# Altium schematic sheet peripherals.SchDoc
size A3
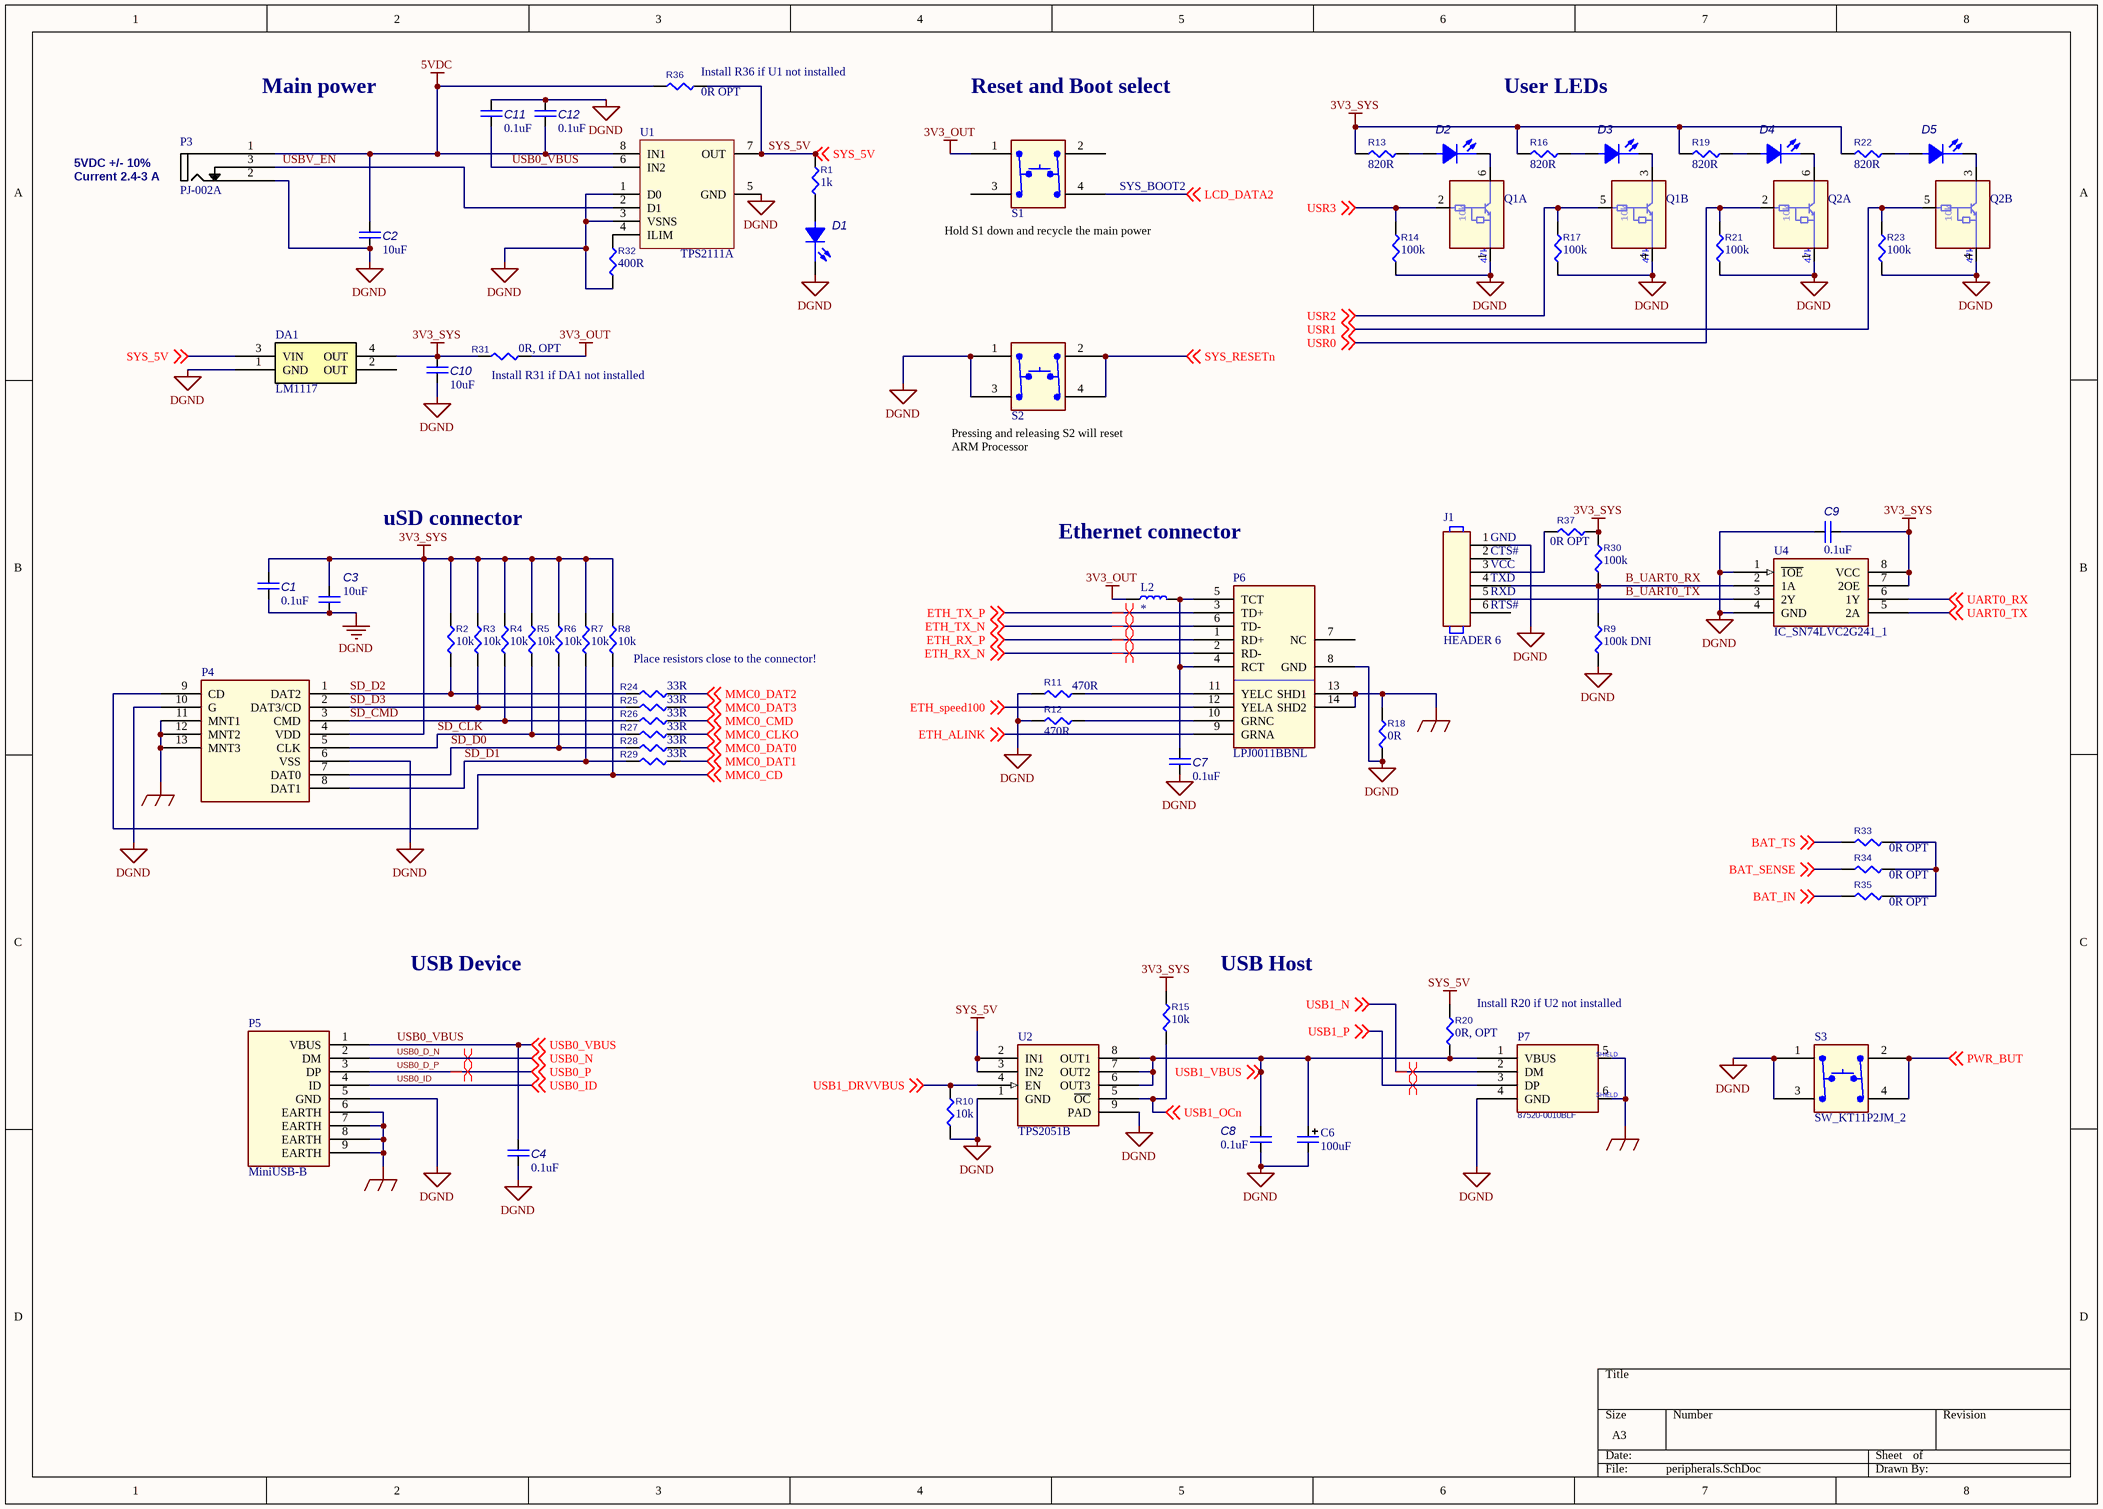
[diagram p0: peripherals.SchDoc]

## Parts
C1  value 0.1uF  [CC1608-0603]  (hidden comment: C0603)
C2  value 10uF  [CC2012-0805]  (hidden comment: C0805)
C3  value 10uF  [CC2012-0805]  (hidden comment: C0805)
C4  value 0.1uF  [CC1608-0603]  (hidden comment: C0603)
C6  value 100uF  [Cap_C]  (hidden comment: Cap_C)
C7  value 0.1uF  [CC1608-0603]  (hidden comment: C0603)
C8  value 0.1uF  [CC1608-0603]  (hidden comment: C0603)
C9  value 0.1uF  [CC1608-0603]  (hidden comment: C0603)
C10  value 10uF  [CC2012-0805]  (hidden comment: C0805)
C11  value 0.1uF  [CC1608-0603]  (hidden comment: C0603)
C12  value 0.1uF  [CC1608-0603]  (hidden comment: C0603)
D1  LED0805  [LED0805]  (value not drawn)
D2  LED0805  [LED0805]  (value not drawn)
D3  LED0805  [LED0805]  (value not drawn)
D4  LED0805  [LED0805]  (value not drawn)
D5  LED0805  [LED0805]  (value not drawn)
DA1  LM1117  [SOT230P700X160-4N]
J1  HEADER 6  [DIP6]
L2  BLM18A-FB  [CHIP0603]  (value not drawn)
P3  PJ-002A  [PJ-002A]
P4  (no value)  [TFC08WP01F-A-R1K-H]
P5  MiniUSB-B  [MINI-USB-B5 SMT]
P6  P/N: LPJ0011BBNL  [TRJ0011ABNL]  (hidden comment: CONN_RJ45_MAG_WE_0)
P7  P/N: 87520-0010BLF  [USB2.5-2H4C]  (hidden comment: CONN_54819-0578_2)
Q1  RN1907  [SOT363-6L]  (value not drawn)  (parts A,B of 2)
Q2  RN1907  [SOT363-6L]  (value not drawn)  (parts A,B of 2)
R1  value 1k  [RESC1608X55N]  (hidden comment: R0603)
R2  value 10k  [RESC1608X55N]  (hidden comment: R0603)
R3  value 10k  [RESC1608X55N]  (hidden comment: R0603)
R4  value 10k  [RESC1608X55N]  (hidden comment: R0603)
R5  value 10k  [RESC1608X55N]  (hidden comment: R0603)
R6  value 10k  [RESC1608X55N]  (hidden comment: R0603)
R7  value 10k  [RESC1608X55N]  (hidden comment: R0603)
R8  value 10k  [RESC1608X55N]  (hidden comment: R0603)
R9  value 100k DNI  [RESC1608X55N]  (hidden comment: R0603)
R10  value 10k  [RESC1608X55N]  (hidden comment: R0603)
R11  value 470R  [RESC1608X55N]  (hidden comment: R0603)
R12  value 470R  [RESC1608X55N]  (hidden comment: R0603)
R13  value 820R  [RESC1608X55N]  (hidden comment: R0603)
R14  value 100k  [RESC1608X55N]  (hidden comment: R0603)
R15  value 10k  [RESC1608X55N]  (hidden comment: R0603)
R16  value 820R  [RESC1608X55N]  (hidden comment: R0603)
R17  value 100k  [RESC1608X55N]  (hidden comment: R0603)
R18  value 0R  [RESC1608X55N]  (hidden comment: R0603)
R19  value 820R  [RESC1608X55N]  (hidden comment: R0603)
R20  value 0R, OPT  [RESC1608X55N]  (hidden comment: R0603)
R21  value 100k  [RESC1608X55N]  (hidden comment: R0603)
R22  value 820R  [RESC1608X55N]  (hidden comment: R0603)
R23  value 100k  [RESC1608X55N]  (hidden comment: R0603)
R24  value 33R  [RESC1608X55N]  (hidden comment: R0603)
R25  value 33R  [RESC1608X55N]  (hidden comment: R0603)
R26  value 33R  [RESC1608X55N]  (hidden comment: R0603)
R27  value 33R  [RESC1608X55N]  (hidden comment: R0603)
R28  value 33R  [RESC1608X55N]  (hidden comment: R0603)
R29  value 33R  [RESC1608X55N]  (hidden comment: R0603)
R30  value 100k  [RESC1608X55N]  (hidden comment: R0603)
R31  value 0R, OPT  [RESC1608X55N]  (hidden comment: R0603)
R32  value 400R  [RESC1608X55N]  (hidden comment: R0603)
R33  value 0R OPT  [RESC1608X55N]  (hidden comment: R0603)
R34  value 0R OPT  [RESC1608X55N]  (hidden comment: R0603)
R35  value 0R OPT  [RESC1608X55N]  (hidden comment: R0603)
R36  value 0R OPT  [RESC1608X55N]  (hidden comment: R0603)
R37  value 0R OPT  [RESC1608X55N]  (hidden comment: R0603)
S1  SW_KT11P2JM_2  [KMR231GLFS]  (value not drawn)
S2  SW_KT11P2JM_2  [KMR231GLFS]  (value not drawn)
S3  SW_KT11P2JM_2  [KMR231GLFS]
U1  P/N: TPS2111A  [TSSOP-8]  (hidden comment: TPS211xA)
U2  TPS2051B  [R-PDSO-G8]
U4  IC_SN74LVC2G241_1  [SOP127P600-8N]

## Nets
3V3_OUT: L2.1 R31.2 S1.1(A1)
3V3_SYS: C1.1 C3.2 C9.2 C10.2 DA1.4(OUT) P4.4(VDD) R2.2 R3.2 R4.2 R5.2 R6.2 R7.2 R8.2 R13.2 R15.2 R16.2 R19.2 R22.2 R30.2 R31.1 R37.2 U4.7(2OE) U4.8(VCC)
5VDC: C2.2 C12.2 P3.1(GND) R36.1 U1.8(IN1)
DGND: C1.2 C2.1 C3.1 C4.2 C6.2 C7.2 C8.1 C9.1 C10.1 C11.1 C12.1 D1.2(C) DA1.1(GND) J1.1 P3.2(RIGHT) P4.6(VSS) P4.10(G) P5.5(GND) P6.8(GND) P7.4(GND) Q1.1 Q1.4 Q2.1 Q2.4 R9.1 R10.1 R11.1 R12.1 R14.1 R17.1 R18.1 R21.1 R23.1 R32.2 S2.1(A1) S2.3(A2) S3.1(A1) S3.3(A2) U1.1(D0) U1.3(VSNS) U1.5(GND) U2.1(GND) U2.9(PAD) U4.1(~{1OE}) U4.4(GND)
EARTH: P4.11(MNT1) P4.12(MNT2) P4.13(MNT3) P5.6(EARTH) P5.7(EARTH) P5.8(EARTH) P5.9(EARTH) P6.13(SHD1) P6.14(SHD2) P7.5(SHELD1) P7.6(PAD4) R18.2
SYS_5V: DA1.3(VIN) R1.2 R20.2 R36.2 U1.7(OUT) U2.2(IN1) U2.3(IN2) ; off-sheet SYS_5V
B_UART0_RX: J1.4 R9.2 R30.1 U4.2(1A)
B_UART0_TX: J1.5 U4.3(2Y)
BAT_IN: R35.1 ; off-sheet BAT_IN
BAT_SENSE: R34.1 ; off-sheet BAT_SENSE
BAT_TS: R33.1 ; off-sheet BAT_TS
ETH_ALINK: P6.9(GRNA) ; off-sheet ETH_ALINK
ETH_RX_N: P6.2(RD-) ; off-sheet ETH_RX_N
ETH_RX_P: P6.1(RD+) ; off-sheet ETH_RX_P
ETH_speed100: P6.12(YELA) ; off-sheet ETH_speed100
ETH_TX_N: P6.6(TD-) ; off-sheet ETH_TX_N
ETH_TX_P: P6.3(TD+) ; off-sheet ETH_TX_P
LCD_DATA2: S1.4(B2) ; off-sheet LCD_DATA2
MMC0_CD: P4.9(CD) R8.1 ; off-sheet MMC0_CD
MMC0_CLKO: R27.2 ; off-sheet MMC0_CLKO
MMC0_CMD: R26.2 ; off-sheet MMC0_CMD
MMC0_DAT0: R28.2 ; off-sheet MMC0_DAT0
MMC0_DAT1: R29.2 ; off-sheet MMC0_DAT1
MMC0_DAT2: R24.2 ; off-sheet MMC0_DAT2
MMC0_DAT3: R25.2 ; off-sheet MMC0_DAT3
PWR_BUT: S3.2(B1) S3.4(B2) ; off-sheet PWR_BUT
SD_CLK: P4.5(CLK) R5.1 R27.1
SD_CMD: P4.3(CMD) R4.1 R26.1
SD_D0: P4.7(DAT0) R6.1 R28.1
SD_D1: P4.8(DAT1) R7.1 R29.1
SD_D2: P4.1(DAT2) R2.1 R24.1
SD_D3: P4.2(DAT3/CD) R3.1 R25.1
SYS_RESETn: S2.2(B1) S2.4(B2) ; off-sheet SYS_RESETn
UART0_RX: U4.6(1Y) ; off-sheet UART0_RX
UART0_TX: U4.5(2A) ; off-sheet UART0_TX
USB0_D_N: P5.2(DM) ; off-sheet USB0_N  [also labelled USB0_N]
USB0_D_P: P5.3(DP) ; off-sheet USB0_P  [also labelled USB0_P]
USB0_ID: P5.4(ID) ; off-sheet USB0_ID
USB0_VBUS: C4.1 C11.2 P5.1(VBUS) U1.6(IN2) ; off-sheet USB0_VBUS
USB1_DRVVBUS: R10.2 U2.4(EN) ; off-sheet USB1_DRVVBUS
USB1_N: P7.2(DM) ; off-sheet USB1_N
USB1_OCn: R15.1 U2.5(~{OC}) ; off-sheet USB1_OCn
USB1_P: P7.3(DP) ; off-sheet USB1_P
USB1_VBUS: C6.1 C8.2 P7.1(VBUS) R20.1 U2.6(OUT3) U2.7(OUT2) U2.8(OUT1) ; off-sheet USB1_VBUS
USBV_EN: P3.3(LEFT) U1.2(D1)
USR0: Q2.2 R21.2 ; off-sheet USR0
USR1: Q2.5 R23.2 ; off-sheet USR1
USR2: Q1.5 R17.2 ; off-sheet USR2
USR3: Q1.2 R14.2 ; off-sheet USR3
NetC7_1: C7.1 L2.2 P6.4(RCT) P6.5(TCT)
NetD1_1: D1.1(A) R1.1
NetD2_1: D2.1(A) R13.1
NetD2_2: D2.2(C) Q1.6
NetD3_1: D3.1(A) R16.1
NetD3_2: D3.2(C) Q1.3
NetD4_1: D4.1(A) R19.1
NetD4_2: D4.2(C) Q2.6
NetD5_1: D5.1(A) R22.1
NetD5_2: D5.2(C) Q2.3
NetJ1_3: J1.3 R37.1
NetP6_10: P6.10(GRNC) R12.2
NetP6_11: P6.11(YELC) R11.2
NetR32_1: R32.1 U1.4(ILIM)
NetR33_2: R33.2 R34.2 R35.2

Not connected (* = marked no-connect by the designer): DA1 2(OUT); J1 2 6; P6 7(NC); S1 2(B1) 3(A2)

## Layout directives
differential pair: ETH_RX_N, ETH_RX_P, ETH_TX_N, ETH_TX_P, USB0_D_N, USB0_D_P, USB1_N, USB1_P

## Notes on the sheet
- Main power
- (near R36) Install R36 if U1 not installed
- Reset and Boot select
- User LEDs
- 5VDC +/- 10%
  Current 2.4-3 A
- SYS_BOOT2
- (near S1) Hold S1 down and recycle the main power
- (near R31) Install R31 if DA1 not installed
- (near S2) Pressing and releasing S2 will reset ARM Processor
- uSD connector
- Ethernet connector
- (near J1) GND
- (near J1) CTS#
- (near J1) VCC
- (near J1) TXD
- (near J1) RXD
- (near J1) RTS#
- Place resistors close to the connector!
- USB Device
- USB Host
- (near R20) Install R20 if U2 not installed

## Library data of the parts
C6 = Cap_C: Tantalum Capacitor Case C
D1-D5 = LED0805: LED 0805
DA1 = LM1117: 800mA Low-Dropout Linear Regulator; Manufacturer: National; Man P/N: LM1117IMPX-3.3, OPT
J1 = HEADER 6: CONN HEADER 6POS, VERTICAL,  .100 STR TIN; Mfr: FCI; P/N: 68000-406HLF
L2 = BLM18A-FB: Chip EMIFILr Inductor Type; Manufacturer: Murata
P3 = PJ-002A: DC POWER JACK; Manufacturer: CIU Inc; Vendor: Digi-key; Alternative P/N: DJK-02A
P4 = TFC08WP01F-R1K-H-CN: Connector for microSD™ Card (Push-push Type); Mfr: AUK Contractors Co, LTD
P5 = MiniUSB-B: Mini USB Type B CONNECTOR; Mfr: Hirose; P/N: UX60SC-MB-5ST(80)
P6 = CONN_RJ45_MAG_WE_0: RJ-45 10/100 W/Magnetics; Mfr: Link PP; P/N-2: Wurth 7499011212
P7 = CONN_54819-0578_2: USB Type A Connectors; Mfr: FCI
Q1 Q2 = RN1907: Transistor Silicon NPN; Mfr: ONS; P/N: MUN5211DW1T1G
S1-S3 = SW_KT11P2JM_2: SMD button; Mfr: C&K Components
U1 = TPS211xA: Single Channel, Current-Limited USB Power Distribution Switch; Manufacturer: TI
U2 = TPS2051B: CURRENT-LIMITED, POWER-DISTRIBUTION SWITCHES; Mfr: TI; P/N: TPS2051BDGN
U4 = IC_SN74LVC2G241_1: Dual Buffer/Driver With 3-State Outputs; Mfr: TI; P/N: SN74LVC2G241DCU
